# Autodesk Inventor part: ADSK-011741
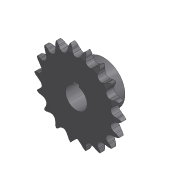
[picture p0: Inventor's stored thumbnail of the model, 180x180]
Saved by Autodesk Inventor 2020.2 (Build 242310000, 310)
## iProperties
Created: 1999-12
Part Number: ADSK-011741
Material: Acier (alliage faible hypertrempé)
Description: SPROCKET,B,40B18,0.750B,0.18 KEY
Document SubType Name: Modeling
Designer: gpurviance
Density: 7.84 g/cm^3
Appearance: Metal-Steel(Polish)
Mass: 330.592 g
Surface Area: 135.889 cm^2
Volume: 42.1674 cm^3
Control State: 0
Master: False
Checked Out: False
Shininess: 0.0
Length Units: 11269
Angle Units: 11279
Time Units: 11290
Mass Units: 11283
Length Display Precision: 3
Angle Display Precision: 2
Compacted: True
Material Desc: SPROCKET,B,40B
Material_number: A08xxxx
Dimensions: 80x25,4x81,2 mm
Mass: 0,331 kg
VLT_Material: Acier (alliage faible hypertrempé)
Density: 0.0
Volumn: 0.0
Area: 0.0
PropertySet Name: Model Information
Author: gpurviance
Revision Number: -
Title: SPROCKET,B,40B18,0.750B,0.18 KEY
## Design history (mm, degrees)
node "Solide1"
node "Corps solides"
node "Corps surfaciques"
node "Sprocket blank" dims "d1" = 7.2136 (= thk), "d2" = 0
node "Half of tooth shape" dims "d15" = 7.2136 (= thk), "d16" = 0
node "Sprocket centerline"
node "Hub" dims "d28" = 18.1864 (= hubthk), "d29" = 0
node "Bore extrusion" dims "d31" = 18.1864 (= hubthk), "d32" = 0 (computed from Taper)
node "Mirror of tooth half"
node "tooth array" dims "d17" = 180 (= N_1), "d19" = 20 deg (computed from N_1)
node "Revolution2" dims "d46" = 90 deg
node "Extrusion6" dims "d52" = 25.4, "d53" = 0
workplane "Arbeitsebene1"
sketch "Sketch1"
  geometry: C1 r 32.606 at (0, 0)
  constraints: 1 centre point
  dimensions: "d0" = 32.60579 radius of C1 (computed from N_1, Pitch, Dr)
sketch "Sketch2" dims "d5" = 7.9248 (= Dr)
  geometry: L1 (0, 39.127)-(0, 0); L2 (0, 0)-(13.382, 36.767); L3 (0, 0)-(6.794, 38.533); L4 (0, 36.568)-(-7.642, 36.568); L5 (3.108, 34.111)-(-4.973, 40.5); L6 (-4.973, 40.5)-(7.538, 35.075); L7 (-11.233, 44.251)-(20.947, 30.296); L8 (4.479, 36.402)-(4.857, 37.274); L9 (24.139, 65.256)-(10.873, 34.665); L10 (7.052, 39.994)-(5.662, 32.11); C1 r 32.606 at (0, 0) reference; C2 r 43.904 at (0, 0); A1 r 3.962 centre (0, 36.568) between (0, 32.606) and (3.108, 34.111); A2 r 10.302 centre (-4.973, 40.5) between (3.108, 34.111) and (4.479, 36.402); A3 r 6.558 centre (10.873, 34.665) between (7.052, 39.994) and (4.857, 37.274); A4 r 32.606 centre (0, 0) between (5.662, 32.11) and (0, 32.606)
  constraints: 20 end point, 8 point on circle, 5 centre point, 5 point on line, 4 coincident, 2 equal length, 2 tangent, 1 collinear, 1 horizontal, 1 midpoint, 1 parallel, 1 vertical, 1 vertical alignment, 3 other
  dimensions: "d7" = 10 deg angle of L3 L1 (computed from N_1); "d8" = 10 deg angle of L2 L3 (= d7); "d9" = 38.3333 deg angle of L5 L4 (computed from N_1); "d10" = 14.8889 deg angle of L6 L5 (computed from N_1); "d11" = 6.33984 distance of L4.start L5.end (= 0.8 x Dr); "d12" = 0.95056 distance between parallel lines of L6 L7 (computed from Dr, N_1); "d13" = 39.12695 distance of L1.end L2.end (= 1.2 x d0); "d14" = 6.55751 distance between parallel lines of L9 L8 (computed from N_1, Dr); "d33" = 32.60579 radius of A4 (= d0); "d48" = 87.8078 diameter of C2
sketch "Sketch5"
  geometry: C1 r 32.606 at (0, 0) reference; C2 r 19.844 at (0, 0)
  constraints: 1 centre point, 1 coincident
  dimensions: "d27" = 39.6875 diameter of C2 (= hubdia)
sketch "Sketch6"
  geometry: C1 r 19.844 at (0, 0) reference; C2 r 10 at (0, 0)
  constraints: 1 centre point, 1 coincident
  dimensions: "d30" = 20 diameter of C2 (= bore)
sketch "Sketch7"
  geometry: L1 (7.214, -8.005)-(7.214, 0) reference; L2 (0, 0)-(7.214, 0) reference; L3 (0, -8.005)-(0, 0) reference; L4 (1.575, 0)-(0, -6.35); L5 (5.639, 0)-(7.214, -6.35); L6 (0, 0)-(-3.607, 0); L7 (-3.607, 0)-(-3.607, -13.564); L8 (-3.607, -13.564)-(0, -13.564); L9 (0, -13.564)-(0, 0); L10 (-5.771, -40.611)-(9.378, -40.611) reference
  constraints: 12 end point, 4 point on line, 2 parallel, 1 horizontal, 1 perpendicular
  dimensions: "d40" = 1.5748 distance from line of L4.start L3 (= G); "d41" = 1.5748 distance from line of L5.start L1 (= G); "d42" = 6.35 distance from line of L5.end L2 (= h); "d43" = 6.35 distance from line of L4.end L2 (= h); "d44" = 7.2136 distance from line of L8 L5.end (= thk); "d45" = 3.6068 distance between parallel lines of L3 L7 (= 0.5 x thk)
sketch "Sketch8"
  geometry: L1 (0, 0)-(0, 12); L2 (0, 12)-(2.5, 12); L3 (2.5, 12)-(2.5, 9.682); L4 (0, 12)-(-2.5, 12); L5 (-2.5, 12)-(-2.5, 9.682); C1 r 19.844 at (0, 0) reference; A1 r 10 centre (0, 0) between (2.5, 9.682) and (-2.5, 9.682) reference
  constraints: 10 end point, 4 perpendicular, 2 point on circle, 1 vertical
  dimensions: "d49" = 12 distance of L1.start L1.end; "d50" = 5 distance between parallel lines of L3 L5; "d51" = 2.5 distance between parallel lines of L1 L5 (= 0.5 x d50)
other parameters: "Pitch" = 12.7 [user parameter; used in 1 equation term], "Dr" = 7.9248 [user parameter; used in 5 equation terms], "thk" = 7.2136 [user parameter; used in 4 equation terms], "h" = 6.35 [user parameter; used in 2 equation terms], "G" = 1.5748 [user parameter; used in 2 equation terms], "hubdia" = 39.6875 [user parameter; used in 1 equation term], "hubthk" = 18.1864 [user parameter; used in 2 equation terms], "bore" = 20 [user parameter; used in 1 equation term], "Taper" = 0 [user parameter; used in 1 equation term]
